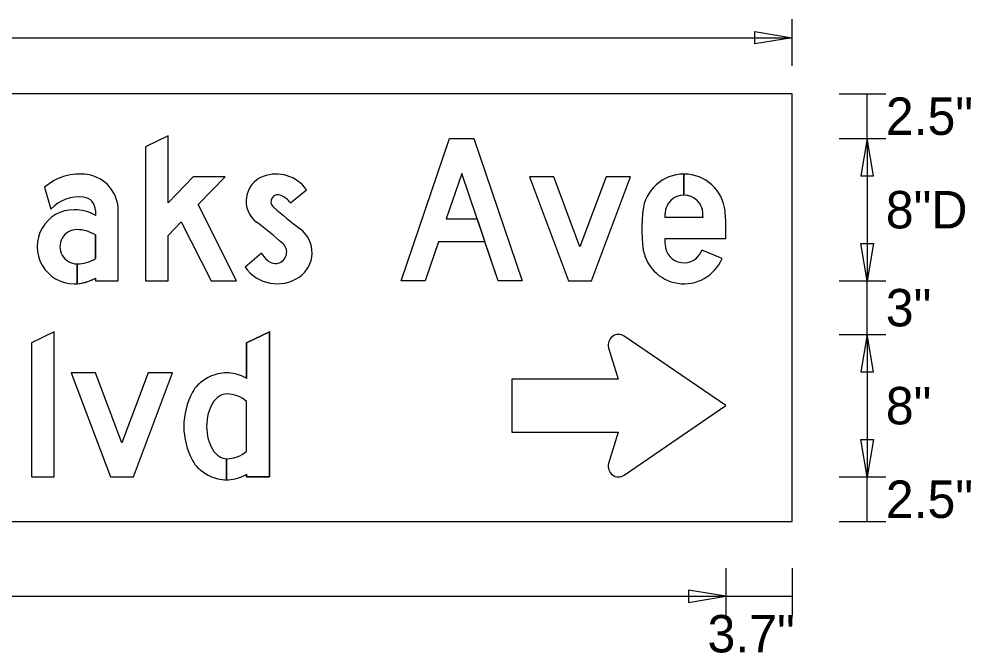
# Model space of a CAD drawing. Extents: x 1374 to 1480, y 568 to 638.
# Drawn here: x 1420.24 to 1424.694, y 624.529 to 627.494 of the extents above; entities that cross this region are included whole.
import ezdxf

# ---------------------------------------------------------------- set-up
doc = ezdxf.new("R2010")
doc.units = 0
for name, color, linetype in [('GSBWFill', 7, 'Continuous'), ('GSColorFill', 7, 'Continuous'), ('GSDims', 7, 'Continuous'), ('GSOutline', 7, 'Continuous')]:
    doc.layers.add(name, color=color, linetype=linetype)

msp = doc.modelspace()

# ---------------------------------------------------------------- linework, layer by layer
at = {"layer": 'GSBWFill'}
for p, q in [((1423.8581, 627.1437), (1414.8581, 627.1437)), ((1423.8581, 625.1437), (1423.8581, 627.1437)), ((1423.3511, 626.6704), (1423.3511, 626.7687)), ((1423.3511, 626.7687), (1423.3511, 626.6704)), ((1420.3592, 626.7066), (1420.3885, 626.604)), ((1421.5098, 626.6337), (1421.5852, 626.6952)), ((1420.5978, 626.5978), (1420.5978, 626.5754)), ((1423.4403, 626.5654), (1423.2619, 626.5654)), ((1420.5978, 626.4837), (1420.5978, 626.3737)), ((1423.2616, 626.467), (1423.5465, 626.467)), ((1423.5293, 626.3734), (1423.4348, 626.4134)), ((1420.5111, 626.3487), (1420.5111, 626.2558)), ((1420.5111, 626.2558), (1420.5111, 626.3487)), ((1414.8581, 625.1437), (1423.8581, 625.1437))]:
    msp.add_line(p, q, dxfattribs=at)
for points in [[(1421.0778, 626.6255), (1421.2044, 626.7554), (1421.0554, 626.7554), (1420.9378, 626.6348), (1420.9378, 626.947), (1420.8311, 626.8954), (1420.8311, 626.2687), (1420.9378, 626.2687), (1420.9378, 626.482), (1420.999, 626.5448), (1421.1383, 626.2687), (1421.2578, 626.2687)], [(1422.0278, 626.2687), (1422.2544, 626.9354), (1422.3678, 626.9354), (1422.5944, 626.2687), (1422.4818, 626.2687), (1422.3111, 626.7707), (1422.239, 626.5586), (1422.3831, 626.5586), (1422.4194, 626.452), (1422.2027, 626.452), (1422.1404, 626.2687)], [(1422.8106, 626.2687), (1422.9183, 626.2687), (1423.1011, 626.7554), (1422.9871, 626.7554), (1422.8644, 626.4287), (1422.7417, 626.7554), (1422.6278, 626.7554)], [(1420.4044, 625.352), (1420.4044, 626.0304), (1420.2978, 625.9787), (1420.2978, 625.352)], [(1420.6673, 625.352), (1420.7749, 625.352), (1420.9578, 625.8387), (1420.8438, 625.8387), (1420.7211, 625.512), (1420.5984, 625.8387), (1420.4844, 625.8387)]]:
    msp.add_lwpolyline(points, close=True, dxfattribs=at)
for points in [[(1420.5978, 626.282), (1420.5978, 626.2687), (1420.7044, 626.2687), (1420.7044, 626.5978)], [(1421.3984, 626.3693), (1421.3741, 626.398), (1421.2978, 626.3334)], [(1421.3044, 625.8129), (1421.3044, 625.9787), (1421.4111, 626.0304), (1421.4111, 625.352), (1421.3044, 625.352), (1421.3044, 625.3645)], [(1423.072, 625.3605), (1423.5465, 625.6854), (1423.072, 626.0103)], [(1422.9988, 625.9565), (1423.044, 625.8091), (1422.5465, 625.8091)], [(1422.5465, 625.8091), (1422.5465, 625.5617), (1423.044, 625.5617), (1422.9988, 625.4143)], [(1421.3044, 625.472), (1421.3044, 625.7054)], [(1421.2111, 625.437), (1421.2111, 625.3387)], [(1421.2111, 625.3387), (1421.2111, 625.437)]]:
    msp.add_lwpolyline(points, dxfattribs=at)
for centre, start, end in [((1423.0448, 625.9706), 55.6003, 197.0573), ((1423.0448, 625.4002), 162.9427, 304.3997)]:
    msp.add_arc(centre, 0.0481, start, end, dxfattribs=at)
for centre, major_axis, ratio, start_param, end_param in [((1420.5228, 626.522), (0, 0.2467), 0.999996, 6.131534, 7.008559), ((1420.5344, 626.5978), (0, 0.17), 0.999996, 4.712389, 6.131534), ((1421.4258, 626.6421), (0, 0.1233), 0.999995, 0.361084, 2.488009), ((1421.4435, 626.5954), (0, 0.1733), 0.999995, 5.326111, 6.644269), ((1423.3511, 626.5752), (0, 0.1935), 0.999996, 0, 1.470576), ((1423.3511, 626.5752), (0, 0.1935), 0.999996, 4.81261, 6.283013), ((1420.5208, 626.482), (0, 0.18), 0.999996, 6.165734, 7.108689), ((1421.4518, 626.6389), (0, 0.0333), 0.999995, 5.821908, 8.713004), ((1421.4102, 626.5554), (0, 0.1267), 0.999995, 5.379051, 5.821908), ((1423.3511, 626.5818), (0, 0.0886), 0.999996, 0, 1.530173), ((1423.3511, 626.5818), (0, 0.0886), 0.999996, 4.753012, 6.282809), ((1420.5344, 626.5978), (0, 0.0633), 0.999996, 4.712389, 6.165734), ((1420.4978, 626.4287), (0, 0.1733), 0.999996, 0, 3.141593), ((1420.4978, 626.4012), (0, 0.2008), 0.999996, 5.761981, 6.283185), ((1423.2262, 628.696), (0, 2.75), 0.999995, 2.429818, 2.489268), ((1423.9793, 626.512), (0, 0.8248), 0.999996, 1.470576, 1.570796), ((1425.0671, 626.512), (0, 1.8061), 0.999996, 1.530173, 1.541262), ((1421.635, 626.512), (0, 1.8061), 0.999996, 4.741924, 4.753012), ((1422.7229, 626.512), (0, 0.8248), 0.999996, 4.712389, 4.81261), ((1419.6787, 624.361), (0, 2.75), 0.999995, 5.571913, 5.629602), ((1420.5111, 626.4287), (0, 0.08), 0.999996, 0, 3.141593), ((1420.5111, 626.346), (0, 0.1627), 0.999996, 5.72151, 6.283185), ((1421.4731, 626.401), (0, 0.138), 0.999995, 3.732982, 5.630861), ((1423.9793, 626.512), (0, 0.8248), 0.999996, 1.570796, 1.671017), ((1422.7229, 626.512), (0, 0.8248), 0.999996, 4.657806, 4.712389), ((1421.4391, 626.4038), (0, 0.0533), 0.999995, 2.273512, 5.571913), ((1425.0671, 626.512), (0, 1.8061), 0.999996, 1.595715, 1.61142), ((1423.3511, 626.4489), (0, 0.1935), 0.999996, 1.671017, 4.311605), ((1423.3511, 626.4423), (0, 0.0886), 0.999996, 1.61142, 4.380076), ((1420.5111, 626.5114), (0, 0.1627), 0.999996, 3.141798, 3.703268), ((1421.4478, 626.4387), (0, 0.1833), 0.999995, 2.182616, 3.732982), ((1420.4978, 626.4562), (0, 0.2008), 0.999996, 3.208198, 3.662797), ((1420.4978, 626.4562), (0, 0.2008), 0.999996, 3.141593, 3.208032), ((1421.2274, 625.6243), (0, 0.2181), 0.999999, 0.454071, 0.759609), ((1421.2111, 625.6577), (0, 0.181), 0.999999, 6.283185, 6.737256), ((1421.2111, 625.6577), (0, 0.181), 0.999999, 5.829115, 6.283185), ((1421.1948, 625.6243), (0, 0.2181), 0.999999, 5.756638, 5.829115), ((1421.169, 625.6858), (0, 0.1333), 0.999999, 0.759609, 1.075368), ((1421.3487, 625.5887), (0, 0.3376), 0.999999, 1.075368, 2.066224), ((1421.2408, 625.637), (0, 0.1124), 0.999999, 0.592441, 1.019141), ((1421.2111, 625.6812), (0, 0.0591), 0.999999, 6.283185, 6.875627), ((1421.2111, 625.5984), (0, 0.1419), 0.999999, 5.565644, 6.283185), ((1421.2882, 625.6078), (0, 0.1681), 0.999999, 1.019141, 1.321211), ((1421.3634, 625.5887), (0, 0.2456), 0.999999, 1.321211, 1.570796), ((1421.3634, 625.5887), (0, 0.2456), 0.999999, 1.570796, 1.820382), ((1421.2882, 625.5695), (0, 0.1681), 0.999999, 1.820382, 2.122451), ((1421.2408, 625.5404), (0, 0.1124), 0.999999, 2.122451, 2.549151), ((1421.2111, 625.579), (0, 0.1419), 0.999999, 3.14171, 3.859134), ((1421.169, 625.4916), (0, 0.1333), 0.999999, 2.066224, 2.381983), ((1421.2111, 625.4962), (0, 0.0591), 0.999999, 2.549151, 3.141593), ((1421.2274, 625.5531), (0, 0.2181), 0.999999, 2.381983, 2.687522), ((1421.2111, 625.5197), (0, 0.181), 0.999999, 2.687522, 3.141593), ((1421.2111, 625.5197), (0, 0.181), 0.999999, 3.141685, 3.595663), ((1421.1948, 625.5531), (0, 0.2181), 0.999999, 3.595663, 3.66814)]:
    msp.add_ellipse(centre, major_axis=major_axis, ratio=ratio, start_param=start_param, end_param=end_param, dxfattribs=at)
at = {"layer": 'GSColorFill'}
for p, q in [((1423.8581, 627.1437), (1414.8581, 627.1437)), ((1423.8581, 627.1437), (1414.8581, 627.1437)), ((1423.8581, 625.1437), (1423.8581, 627.1437)), ((1423.8581, 625.1437), (1423.8581, 627.1437)), ((1423.3511, 626.6704), (1423.3511, 626.7687)), ((1423.3511, 626.7687), (1423.3511, 626.6704)), ((1420.3592, 626.7066), (1420.3885, 626.604)), ((1421.5098, 626.6337), (1421.5852, 626.6952)), ((1420.5978, 626.5978), (1420.5978, 626.5754)), ((1423.4403, 626.5654), (1423.2619, 626.5654)), ((1420.5978, 626.4837), (1420.5978, 626.3737)), ((1423.2616, 626.467), (1423.5465, 626.467)), ((1423.5293, 626.3734), (1423.4348, 626.4134)), ((1420.5111, 626.3487), (1420.5111, 626.2558)), ((1420.5111, 626.2558), (1420.5111, 626.3487)), ((1414.8581, 625.1437), (1423.8581, 625.1437)), ((1414.8581, 625.1437), (1423.8581, 625.1437))]:
    msp.add_line(p, q, dxfattribs=at)
for points in [[(1421.0778, 626.6255), (1421.2044, 626.7554), (1421.0554, 626.7554), (1420.9378, 626.6348), (1420.9378, 626.947), (1420.8311, 626.8954), (1420.8311, 626.2687), (1420.9378, 626.2687), (1420.9378, 626.482), (1420.999, 626.5448), (1421.1383, 626.2687), (1421.2578, 626.2687)], [(1422.0278, 626.2687), (1422.2544, 626.9354), (1422.3678, 626.9354), (1422.5944, 626.2687), (1422.4818, 626.2687), (1422.3111, 626.7707), (1422.239, 626.5586), (1422.3831, 626.5586), (1422.4194, 626.452), (1422.2027, 626.452), (1422.1404, 626.2687)], [(1422.8106, 626.2687), (1422.9183, 626.2687), (1423.1011, 626.7554), (1422.9871, 626.7554), (1422.8644, 626.4287), (1422.7417, 626.7554), (1422.6278, 626.7554)], [(1420.4044, 625.352), (1420.4044, 626.0304), (1420.2978, 625.9787), (1420.2978, 625.352)], [(1420.6673, 625.352), (1420.7749, 625.352), (1420.9578, 625.8387), (1420.8438, 625.8387), (1420.7211, 625.512), (1420.5984, 625.8387), (1420.4844, 625.8387)]]:
    msp.add_lwpolyline(points, close=True, dxfattribs=at)
for points in [[(1420.5978, 626.282), (1420.5978, 626.2687), (1420.7044, 626.2687), (1420.7044, 626.5978)], [(1421.3984, 626.3693), (1421.3741, 626.398), (1421.2978, 626.3334)], [(1421.3044, 625.8129), (1421.3044, 625.9787), (1421.4111, 626.0304), (1421.4111, 625.352), (1421.3044, 625.352), (1421.3044, 625.3645)], [(1423.072, 625.3605), (1423.5465, 625.6854), (1423.072, 626.0103)], [(1422.9988, 625.9565), (1423.044, 625.8091), (1422.5465, 625.8091)], [(1422.5465, 625.8091), (1422.5465, 625.5617), (1423.044, 625.5617), (1422.9988, 625.4143)], [(1421.3044, 625.472), (1421.3044, 625.7054)], [(1421.2111, 625.437), (1421.2111, 625.3387)], [(1421.2111, 625.3387), (1421.2111, 625.437)]]:
    msp.add_lwpolyline(points, dxfattribs=at)
for centre, start, end in [((1423.0448, 625.9706), 55.6003, 197.0573), ((1423.0448, 625.4002), 162.9427, 304.3997)]:
    msp.add_arc(centre, 0.0481, start, end, dxfattribs=at)
for centre, major_axis, ratio, start_param, end_param in [((1420.5228, 626.522), (0, 0.2467), 0.999996, 6.131534, 7.008559), ((1420.5344, 626.5978), (0, 0.17), 0.999996, 4.712389, 6.131534), ((1421.4258, 626.6421), (0, 0.1233), 0.999995, 0.361084, 2.488009), ((1421.4435, 626.5954), (0, 0.1733), 0.999995, 5.326111, 6.644269), ((1423.3511, 626.5752), (0, 0.1935), 0.999996, 0, 1.470576), ((1423.3511, 626.5752), (0, 0.1935), 0.999996, 4.81261, 6.283013), ((1420.5208, 626.482), (0, 0.18), 0.999996, 6.165734, 7.108689), ((1421.4518, 626.6389), (0, 0.0333), 0.999995, 5.821908, 8.713004), ((1421.4102, 626.5554), (0, 0.1267), 0.999995, 5.379051, 5.821908), ((1423.3511, 626.5818), (0, 0.0886), 0.999996, 0, 1.530173), ((1423.3511, 626.5818), (0, 0.0886), 0.999996, 4.753012, 6.282809), ((1420.5344, 626.5978), (0, 0.0633), 0.999996, 4.712389, 6.165734), ((1420.4978, 626.4287), (0, 0.1733), 0.999996, 0, 3.141593), ((1420.4978, 626.4012), (0, 0.2008), 0.999996, 5.761981, 6.283185), ((1423.2262, 628.696), (0, 2.75), 0.999995, 2.429818, 2.489268), ((1423.9793, 626.512), (0, 0.8248), 0.999996, 1.470576, 1.570796), ((1425.0671, 626.512), (0, 1.8061), 0.999996, 1.530173, 1.541262), ((1421.635, 626.512), (0, 1.8061), 0.999996, 4.741924, 4.753012), ((1422.7229, 626.512), (0, 0.8248), 0.999996, 4.712389, 4.81261), ((1419.6787, 624.361), (0, 2.75), 0.999995, 5.571913, 5.629602), ((1420.5111, 626.4287), (0, 0.08), 0.999996, 0, 3.141593), ((1420.5111, 626.346), (0, 0.1627), 0.999996, 5.72151, 6.283185), ((1421.4731, 626.401), (0, 0.138), 0.999995, 3.732982, 5.630861), ((1423.9793, 626.512), (0, 0.8248), 0.999996, 1.570796, 1.671017), ((1422.7229, 626.512), (0, 0.8248), 0.999996, 4.657806, 4.712389), ((1421.4391, 626.4038), (0, 0.0533), 0.999995, 2.273512, 5.571913), ((1425.0671, 626.512), (0, 1.8061), 0.999996, 1.595715, 1.61142), ((1423.3511, 626.4489), (0, 0.1935), 0.999996, 1.671017, 4.311605), ((1423.3511, 626.4423), (0, 0.0886), 0.999996, 1.61142, 4.380076), ((1420.5111, 626.5114), (0, 0.1627), 0.999996, 3.141798, 3.703268), ((1421.4478, 626.4387), (0, 0.1833), 0.999995, 2.182616, 3.732982), ((1420.4978, 626.4562), (0, 0.2008), 0.999996, 3.208198, 3.662797), ((1420.4978, 626.4562), (0, 0.2008), 0.999996, 3.141593, 3.208032), ((1421.2274, 625.6243), (0, 0.2181), 0.999999, 0.454071, 0.759609), ((1421.2111, 625.6577), (0, 0.181), 0.999999, 6.283185, 6.737256), ((1421.2111, 625.6577), (0, 0.181), 0.999999, 5.829115, 6.283185), ((1421.1948, 625.6243), (0, 0.2181), 0.999999, 5.756638, 5.829115), ((1421.169, 625.6858), (0, 0.1333), 0.999999, 0.759609, 1.075368), ((1421.3487, 625.5887), (0, 0.3376), 0.999999, 1.075368, 2.066224), ((1421.2408, 625.637), (0, 0.1124), 0.999999, 0.592441, 1.019141), ((1421.2111, 625.6812), (0, 0.0591), 0.999999, 6.283185, 6.875627), ((1421.2111, 625.5984), (0, 0.1419), 0.999999, 5.565644, 6.283185), ((1421.2882, 625.6078), (0, 0.1681), 0.999999, 1.019141, 1.321211), ((1421.3634, 625.5887), (0, 0.2456), 0.999999, 1.321211, 1.570796), ((1421.3634, 625.5887), (0, 0.2456), 0.999999, 1.570796, 1.820382), ((1421.2882, 625.5695), (0, 0.1681), 0.999999, 1.820382, 2.122451), ((1421.2408, 625.5404), (0, 0.1124), 0.999999, 2.122451, 2.549151), ((1421.2111, 625.579), (0, 0.1419), 0.999999, 3.14171, 3.859134), ((1421.169, 625.4916), (0, 0.1333), 0.999999, 2.066224, 2.381983), ((1421.2111, 625.4962), (0, 0.0591), 0.999999, 2.549151, 3.141593), ((1421.2274, 625.5531), (0, 0.2181), 0.999999, 2.381983, 2.687522), ((1421.2111, 625.5197), (0, 0.181), 0.999999, 2.687522, 3.141593), ((1421.2111, 625.5197), (0, 0.181), 0.999999, 3.141685, 3.595663), ((1421.1948, 625.5531), (0, 0.2181), 0.999999, 3.595663, 3.66814)]:
    msp.add_ellipse(centre, major_axis=major_axis, ratio=ratio, start_param=start_param, end_param=end_param, dxfattribs=at)
at = {"layer": 'GSDims'}
for p, q in [((1423.8581, 627.275), (1423.8581, 627.4937)), ((1414.8581, 627.4062), (1423.8581, 627.4062)), ((1423.8581, 627.275), (1423.8581, 627.275)), ((1424.0769, 627.1437), (1424.2956, 627.1437)), ((1424.0769, 627.1437), (1424.0769, 627.1437)), ((1424.2081, 626.9354), (1424.2081, 627.1437)), ((1424.0769, 626.9354), (1424.2956, 626.9354)), ((1424.0769, 626.9354), (1424.2956, 626.9354)), ((1424.2081, 626.9354), (1424.2081, 626.2687)), ((1424.0769, 626.2687), (1424.2956, 626.2687)), ((1424.0769, 626.2687), (1424.2956, 626.2687)), ((1424.2081, 626.0187), (1424.2081, 626.2687)), ((1424.0769, 626.0187), (1424.2956, 626.0187)), ((1424.0769, 626.0187), (1424.2956, 626.0187)), ((1424.2081, 626.0187), (1424.2081, 625.3521)), ((1424.0769, 625.3521), (1424.2956, 625.3521)), ((1424.0769, 625.3521), (1424.2956, 625.3521)), ((1424.2081, 625.1437), (1424.2081, 625.3521)), ((1424.0769, 625.1437), (1424.2956, 625.1437)), ((1424.0769, 625.1437), (1424.0769, 625.1437)), ((1423.5478, 624.9249), (1423.5478, 624.7062)), ((1423.5478, 624.9249), (1423.5478, 624.7062)), ((1423.8581, 624.9249), (1423.8581, 624.7062)), ((1423.8581, 624.9249), (1423.8581, 624.7062)), ((1415.1678, 624.7937), (1423.5478, 624.7937)), ((1423.5478, 624.7937), (1423.8581, 624.7937))]:
    msp.add_line(p, q, dxfattribs=at)
for points in [[(1423.8581, 627.4062), (1423.6831, 627.377), (1423.6831, 627.4354)], [(1424.2081, 626.9354), (1424.179, 626.7604), (1424.2373, 626.7604)], [(1424.2081, 626.2687), (1424.179, 626.4437), (1424.2373, 626.4437)], [(1424.2081, 626.0187), (1424.179, 625.8437), (1424.2373, 625.8437)], [(1424.2081, 625.3521), (1424.179, 625.5271), (1424.2373, 625.5271)], [(1423.5478, 624.7937), (1423.3728, 624.8229), (1423.3728, 624.7645)]]:
    msp.add_lwpolyline(points, close=True, dxfattribs=at)
at = {"layer": 'GSOutline'}
for p, q in [((1423.8581, 627.1437), (1414.8581, 627.1437)), ((1423.8581, 625.1437), (1423.8581, 627.1437)), ((1420.3592, 626.7066), (1420.3885, 626.604)), ((1421.5098, 626.6337), (1421.5852, 626.6952)), ((1420.5978, 626.5978), (1420.5978, 626.5754)), ((1423.4403, 626.5654), (1423.2619, 626.5654)), ((1420.5978, 626.3737), (1420.5978, 626.4837)), ((1423.2616, 626.467), (1423.5465, 626.467)), ((1423.5293, 626.3734), (1423.4348, 626.4134)), ((1423.4348, 626.4134), (1423.4348, 626.4134)), ((1414.8581, 625.1437), (1423.8581, 625.1437))]:
    msp.add_line(p, q, dxfattribs=at)
for points in [[(1421.0778, 626.6255), (1421.2044, 626.7554), (1421.0554, 626.7554), (1420.9378, 626.6348), (1420.9378, 626.947), (1420.8311, 626.8954), (1420.8311, 626.2687), (1420.9378, 626.2687), (1420.9378, 626.482), (1420.999, 626.5448), (1421.1383, 626.2687), (1421.2578, 626.2687)], [(1422.2027, 626.452), (1422.1404, 626.2687), (1422.0278, 626.2687), (1422.2544, 626.9354), (1422.3678, 626.9354), (1422.5944, 626.2687), (1422.4818, 626.2687), (1422.4194, 626.452)], [(1422.239, 626.5586), (1422.3832, 626.5586), (1422.3111, 626.7707)], [(1422.8106, 626.2687), (1422.9183, 626.2687), (1423.1011, 626.7554), (1422.9871, 626.7554), (1422.8644, 626.4287), (1422.7417, 626.7554), (1422.6278, 626.7554)], [(1420.4044, 625.352), (1420.4044, 626.0304), (1420.2978, 625.9787), (1420.2978, 625.352)], [(1420.6673, 625.352), (1420.7749, 625.352), (1420.9578, 625.8387), (1420.8438, 625.8387), (1420.7211, 625.512), (1420.5984, 625.8387), (1420.4844, 625.8387)]]:
    msp.add_lwpolyline(points, close=True, dxfattribs=at)
for points in [[(1420.5978, 626.282), (1420.5978, 626.2687), (1420.7044, 626.2687), (1420.7044, 626.5978)], [(1421.3984, 626.3693), (1421.3741, 626.398), (1421.2978, 626.3334)], [(1421.3044, 625.3645), (1421.3044, 625.352), (1421.4111, 625.352), (1421.4111, 626.0304), (1421.3044, 625.9787), (1421.3044, 625.8129)], [(1423.072, 625.3605), (1423.5465, 625.6854), (1423.072, 626.0103)], [(1422.9988, 625.9565), (1423.044, 625.8091), (1422.5465, 625.8091)], [(1422.5465, 625.8091), (1422.5465, 625.5617), (1423.044, 625.5617), (1422.9988, 625.4143)], [(1421.3044, 625.472), (1421.3044, 625.7054)]]:
    msp.add_lwpolyline(points, dxfattribs=at)
for centre, start, end in [((1423.0448, 625.9706), 55.6003, 197.0573), ((1423.0448, 625.4002), 162.9427, 304.3997)]:
    msp.add_arc(centre, 0.0481, start, end, dxfattribs=at)
for centre, major_axis, ratio, start_param, end_param in [((1420.5228, 626.522), (0, 0.2467), 0.999996, 6.131534, 7.008559), ((1420.5344, 626.5978), (0, 0.17), 0.999996, 4.712389, 6.131534), ((1421.4258, 626.6421), (0, 0.1233), 0.999995, 0.361084, 2.488009), ((1421.4435, 626.5954), (0, 0.1733), 0.999995, 5.326111, 6.644269), ((1423.3511, 626.5752), (0, 0.1935), 0.999996, 4.81261, 7.753761), ((1420.5208, 626.482), (0, 0.18), 0.999996, 6.165734, 7.108689), ((1421.4518, 626.6389), (0, 0.0333), 0.999995, 5.821908, 8.713004), ((1421.4102, 626.5554), (0, 0.1267), 0.999995, 5.379051, 5.821908), ((1423.3511, 626.5818), (0, 0.0886), 0.999996, 4.753012, 7.813358), ((1420.5344, 626.5978), (0, 0.0633), 0.999996, 4.712389, 6.165734), ((1420.4978, 626.4287), (0, 0.1733), 0.999996, 0, 3.141593), ((1420.4978, 626.4012), (0, 0.2008), 0.999996, 5.761981, 6.283185), ((1423.2262, 628.696), (0, 2.75), 0.999995, 2.429818, 2.489268), ((1423.9793, 626.512), (0, 0.8248), 0.999996, 1.470576, 1.570796), ((1425.0671, 626.512), (0, 1.8061), 0.999996, 1.530173, 1.541262), ((1421.635, 626.512), (0, 1.8061), 0.999996, 4.741924, 4.753012), ((1422.7229, 626.512), (0, 0.8248), 0.999996, 4.712389, 4.81261), ((1419.6787, 624.361), (0, 2.75), 0.999995, 5.571913, 5.629602), ((1420.5111, 626.4287), (0, 0.08), 0.999996, 0, 3.141593), ((1420.5111, 626.346), (0, 0.1627), 0.999996, 5.72151, 6.283185), ((1421.4731, 626.401), (0, 0.138), 0.999995, 3.732982, 5.630861), ((1423.9793, 626.512), (0, 0.8248), 0.999996, 1.570796, 1.671017), ((1422.7229, 626.512), (0, 0.8248), 0.999996, 4.657806, 4.712389), ((1421.4391, 626.4038), (0, 0.0533), 0.999995, 2.273512, 5.571913), ((1425.0671, 626.512), (0, 1.8061), 0.999996, 1.595715, 1.61142), ((1423.3511, 626.4489), (0, 0.1935), 0.999996, 1.671017, 4.311605), ((1423.3511, 626.4423), (0, 0.0886), 0.999996, 1.61142, 4.380076), ((1420.5111, 626.5114), (0, 0.1627), 0.999996, 3.141593, 3.703268), ((1421.4478, 626.4387), (0, 0.1833), 0.999995, 2.182616, 3.732982), ((1420.4978, 626.4562), (0, 0.2008), 0.999996, 3.141593, 3.662797), ((1421.2274, 625.6243), (0, 0.2181), 0.999999, 0.454071, 0.759609), ((1421.2111, 625.6577), (0, 0.181), 0.999999, 6.283185, 6.737256), ((1421.2111, 625.6577), (0, 0.181), 0.999999, 5.829115, 6.283185), ((1421.1948, 625.6243), (0, 0.2181), 0.999999, 5.756638, 5.829115), ((1421.169, 625.6858), (0, 0.1333), 0.999999, 0.759609, 1.075368), ((1421.3487, 625.5887), (0, 0.3376), 0.999999, 1.075368, 2.066224), ((1421.2408, 625.637), (0, 0.1124), 0.999999, 0.592441, 1.019141), ((1421.2111, 625.6812), (0, 0.0591), 0.999999, 6.283185, 6.875627), ((1421.2111, 625.5984), (0, 0.1419), 0.999999, 5.565644, 6.283185), ((1421.2882, 625.6078), (0, 0.1681), 0.999999, 1.019141, 1.321211), ((1421.3634, 625.5887), (0, 0.2456), 0.999999, 1.321211, 1.570796), ((1421.3634, 625.5887), (0, 0.2456), 0.999999, 1.570796, 1.820382), ((1421.2882, 625.5695), (0, 0.1681), 0.999999, 1.820382, 2.122451), ((1421.2408, 625.5404), (0, 0.1124), 0.999999, 2.122451, 2.549151), ((1421.2111, 625.579), (0, 0.1419), 0.999999, 3.141593, 3.859134), ((1421.169, 625.4916), (0, 0.1333), 0.999999, 2.066224, 2.381983), ((1421.2111, 625.4962), (0, 0.0591), 0.999999, 2.549151, 3.141593), ((1421.2274, 625.5531), (0, 0.2181), 0.999999, 2.381983, 2.687522), ((1421.2111, 625.5197), (0, 0.181), 0.999999, 2.687522, 3.141593), ((1421.2111, 625.5197), (0, 0.181), 0.999999, 3.141685, 3.595663), ((1421.2111, 625.5197), (0, 0.181), 0.999999, 3.141593, 3.141685), ((1421.1948, 625.5531), (0, 0.2181), 0.999999, 3.595663, 3.66814)]:
    msp.add_ellipse(centre, major_axis=major_axis, ratio=ratio, start_param=start_param, end_param=end_param, dxfattribs=at)

# ---------------------------------------------------------------- texts
at = {"layer": 'GSDims'}
for s, p in [('2.5"', (1424.2956, 626.952)), ('8"D', (1424.2956, 626.5145)), ('3"', (1424.2956, 626.0562)), ('8"', (1424.2956, 625.5979)), ('2.5"', (1424.2956, 625.1604)), ('3.7"', (1423.4613, 624.5312))]:
    msp.add_text(s, height=0.175, dxfattribs=at).set_placement(p)

doc.saveas('drawing.dxf')
